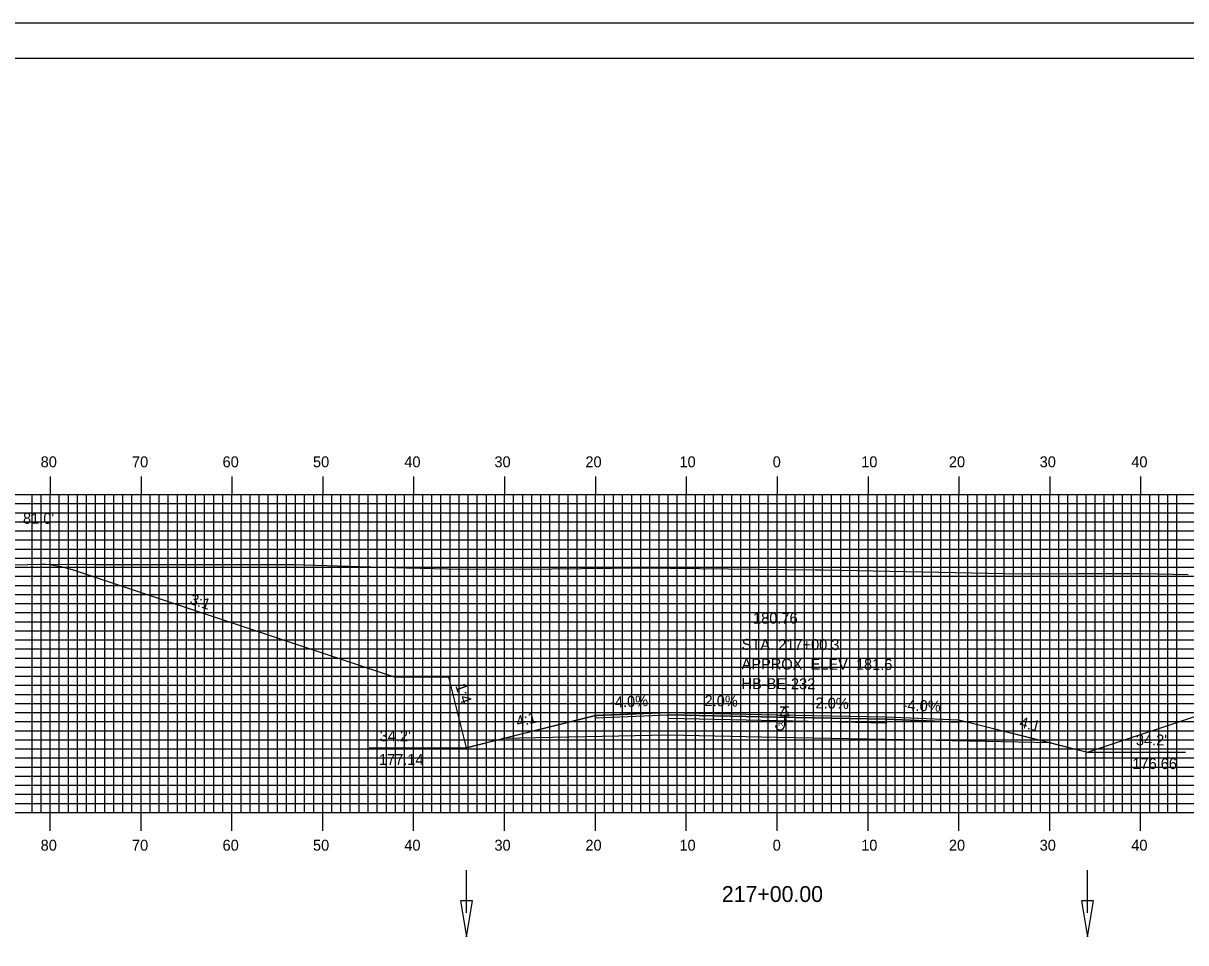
# Model space of a CAD drawing. Extents: x 1796420 to 1796763, y 442591 to 442811.
# Drawn here: x 1796502.9 to 1796630.9, y 442709.3 to 442810.5 of the extents above; entities that cross this region are included whole.
import ezdxf

# ---------------------------------------------------------------- set-up
doc = ezdxf.new("R2010")
doc.units = 0
for name, color, linetype in [('ANNOTATION', 7, 'Continuous'), ('BORDER', 7, 'Continuous'), ('BORING - REFUSAL', 7, 'Continuous'), ('D_Drainage_Ditch_Line', 7, 'Continuous'), ('D_Roadway_Centerline', 7, 'Continuous'), ('D_Roadway_Centerline_Text', 7, 'Continuous'), ('D_Roadway_Edge_Shoulder', 7, 'Continuous'), ('D_Roadway_Edge_TW', 7, 'Continuous'), ('D_Roadway_Pavement', 7, 'Continuous'), ('D_Roadway_SlopeLines', 7, 'Continuous'), ('D_Roadway_SubGrade', 7, 'Continuous'), ('D_Text_Standard', 7, 'Continuous'), ('H_V ANNOTATION', 7, 'Continuous'), ('MAJOR', 7, 'Continuous'), ('MINOR', 7, 'Continuous'), ('PDRAIN', 7, 'Continuous'), ('PLOT BOUNDARY', 7, 'Continuous'), ('S_Roadway_Centerline', 7, 'Continuous')]:
    doc.layers.add(name, color=color, linetype=linetype)

msp = doc.modelspace()

# ---------------------------------------------------------------- linework, layer by layer
at = {"layer": 'BORDER'}
msp.add_lwpolyline([(1796436.31, 442596.67), (1796756.31, 442596.67), (1796756.31, 442806.67), (1796436.31, 442806.67)], close=True, dxfattribs=at)
at = {"layer": 'BORING - REFUSAL'}
for p, q in [((1796587.19, 442735.27), (1796586.23, 442735.27)), ((1796586.71, 442734.31), (1796586.71, 442733.25))]:
    msp.add_line(p, q, dxfattribs=at)
msp.add_lwpolyline([(1796586.71, 442735.27), (1796587.19, 442734.31), (1796586.23, 442734.31)], close=True, dxfattribs=at)
msp.add_arc((1796586.22, 442733.25), 0.485, 180, 0, dxfattribs=at)
at = {"layer": 'D_Drainage_Ditch_Line'}
for p, q in [((1796551.73, 442712.63), (1796551.73, 442717.33)), ((1796620.08, 442712.63), (1796620.08, 442717.33))]:
    msp.add_line(p, q, dxfattribs=at)
for points in [[(1796552.39, 442713.94), (1796551.08, 442713.94), (1796551.73, 442710)], [(1796620.74, 442713.94), (1796619.42, 442713.94), (1796620.08, 442710)]]:
    msp.add_lwpolyline(points, close=True, dxfattribs=at)
at = {"layer": 'D_Roadway_Centerline'}
msp.add_lwpolyline([(1796551.73, 442730.8), (1796555.73, 442731.8), (1796565.91, 442734.35), (1796573.91, 442734.67), (1796585.91, 442734.43), (1796597.91, 442734.19), (1796605.91, 442733.87), (1796616.08, 442731.32), (1796620.08, 442730.32)], dxfattribs=at)
at = {"layer": 'D_Roadway_Edge_Shoulder'}
for points in [[(1796573.91, 442734.67), (1796565.91, 442734.35), (1796565.91, 442734.1), (1796573.91, 442734.42)], [(1796597.91, 442734.19), (1796605.91, 442733.87), (1796605.91, 442733.62), (1796597.91, 442733.94)]]:
    msp.add_lwpolyline(points, close=True, dxfattribs=at)
at = {"layer": 'D_Roadway_Edge_TW'}
msp.add_lwpolyline([(1796573.91, 442734.42), (1796573.91, 442734.67), (1796585.91, 442734.43), (1796597.91, 442734.19), (1796597.91, 442733.94), (1796585.91, 442734.18)], close=True, dxfattribs=at)
at = {"layer": 'D_Roadway_Pavement'}
msp.add_lwpolyline([(1796573.91, 442734), (1796573.91, 442734.42), (1796585.91, 442734.18), (1796597.91, 442733.94), (1796597.91, 442733.52), (1796585.91, 442733.76)], close=True, dxfattribs=at)
at = {"layer": 'D_Roadway_SlopeLines'}
for p, q in [((1796620.08, 442730.32), (1796673.79, 442748.23)), ((1796551.73, 442730.8), (1796549.79, 442738.57))]:
    msp.add_line(p, q, dxfattribs=at)
for points in [[(1796549.79, 442738.57), (1796543.79, 442738.57), (1796508.38, 442750.37)], [(1796565.91, 442734.35), (1796551.73, 442730.8)], [(1796605.91, 442733.87), (1796620.08, 442730.32)]]:
    msp.add_lwpolyline(points, dxfattribs=at)
msp.add_arc((1796504.61, 442739.05), 11.93, 71.5651, 88.398, dxfattribs=at)
at = {"layer": 'D_Roadway_SubGrade'}
msp.add_lwpolyline([(1796573.91, 442732.17), (1796555.73, 442731.8), (1796565.91, 442734.35), (1796565.91, 442734.1), (1796573.91, 442734.42), (1796585.91, 442734.18), (1796597.91, 442733.94), (1796605.91, 442733.62), (1796605.91, 442733.87), (1796616.08, 442731.32), (1796597.91, 442731.69), (1796585.91, 442731.93)], close=True, dxfattribs=at)
at = {"layer": 'MAJOR'}
for p, q in [((1796505.91, 442760.67), (1796505.91, 442758.67)), ((1796515.91, 442760.67), (1796515.91, 442758.67)), ((1796525.91, 442760.67), (1796525.91, 442758.67)), ((1796535.91, 442760.67), (1796535.91, 442758.67)), ((1796545.91, 442760.67), (1796545.91, 442758.67)), ((1796555.91, 442760.67), (1796555.91, 442758.67)), ((1796565.91, 442760.67), (1796565.91, 442758.67)), ((1796575.91, 442760.67), (1796575.91, 442758.67)), ((1796585.91, 442760.67), (1796585.91, 442758.67)), ((1796595.91, 442760.67), (1796595.91, 442758.67)), ((1796605.91, 442760.67), (1796605.91, 442758.67)), ((1796615.91, 442760.67), (1796615.91, 442758.67)), ((1796625.91, 442760.67), (1796625.91, 442758.67)), ((1796445.91, 442758.67), (1796725.91, 442758.67)), ((1796445.91, 442758.67), (1796725.91, 442758.67)), ((1796505.91, 442723.67), (1796505.91, 442758.67)), ((1796515.91, 442723.67), (1796515.91, 442758.67)), ((1796525.91, 442723.67), (1796525.91, 442758.67)), ((1796535.91, 442723.67), (1796535.91, 442758.67)), ((1796545.91, 442723.67), (1796545.91, 442758.67)), ((1796555.91, 442723.67), (1796555.91, 442758.67)), ((1796565.91, 442723.67), (1796565.91, 442758.67)), ((1796575.91, 442723.67), (1796575.91, 442758.67)), ((1796585.91, 442723.67), (1796585.91, 442758.67)), ((1796595.91, 442723.67), (1796595.91, 442758.67)), ((1796605.91, 442723.67), (1796605.91, 442758.67)), ((1796615.91, 442723.67), (1796615.91, 442758.67)), ((1796625.91, 442723.67), (1796625.91, 442758.67)), ((1796445.91, 442753.67), (1796725.91, 442753.67)), ((1796445.91, 442748.67), (1796725.91, 442748.67)), ((1796445.91, 442743.67), (1796725.91, 442743.67)), ((1796445.91, 442738.67), (1796725.91, 442738.67)), ((1796445.91, 442733.67), (1796725.91, 442733.67)), ((1796445.91, 442728.67), (1796725.91, 442728.67)), ((1796445.91, 442723.67), (1796725.91, 442723.67)), ((1796445.91, 442723.67), (1796725.91, 442723.67)), ((1796505.91, 442721.66), (1796505.91, 442723.67)), ((1796515.91, 442721.66), (1796515.91, 442723.67)), ((1796525.91, 442721.66), (1796525.91, 442723.67)), ((1796535.91, 442721.66), (1796535.91, 442723.67)), ((1796545.91, 442721.66), (1796545.91, 442723.67)), ((1796555.91, 442721.66), (1796555.91, 442723.67)), ((1796565.91, 442721.66), (1796565.91, 442723.67)), ((1796575.91, 442721.66), (1796575.91, 442723.67)), ((1796585.91, 442721.66), (1796585.91, 442723.67)), ((1796595.91, 442721.66), (1796595.91, 442723.67)), ((1796605.91, 442721.66), (1796605.91, 442723.67)), ((1796615.91, 442721.66), (1796615.91, 442723.67)), ((1796625.91, 442721.66), (1796625.91, 442723.67))]:
    msp.add_line(p, q, dxfattribs=at)
at = {"layer": 'MINOR'}
for p, q in [((1796503.91, 442723.67), (1796503.91, 442758.67)), ((1796504.91, 442723.67), (1796504.91, 442758.67)), ((1796506.91, 442723.67), (1796506.91, 442758.67)), ((1796507.91, 442723.67), (1796507.91, 442758.67)), ((1796508.91, 442723.67), (1796508.91, 442758.67)), ((1796509.91, 442723.67), (1796509.91, 442758.67)), ((1796510.91, 442723.67), (1796510.91, 442758.67)), ((1796511.91, 442723.67), (1796511.91, 442758.67)), ((1796512.91, 442723.67), (1796512.91, 442758.67)), ((1796513.91, 442723.67), (1796513.91, 442758.67)), ((1796514.91, 442723.67), (1796514.91, 442758.67)), ((1796516.91, 442723.67), (1796516.91, 442758.67)), ((1796517.91, 442723.67), (1796517.91, 442758.67)), ((1796518.91, 442723.67), (1796518.91, 442758.67)), ((1796519.91, 442723.67), (1796519.91, 442758.67)), ((1796520.91, 442723.67), (1796520.91, 442758.67)), ((1796521.91, 442723.67), (1796521.91, 442758.67)), ((1796522.91, 442723.67), (1796522.91, 442758.67)), ((1796523.91, 442723.67), (1796523.91, 442758.67)), ((1796524.91, 442723.67), (1796524.91, 442758.67)), ((1796526.91, 442723.67), (1796526.91, 442758.67)), ((1796527.91, 442723.67), (1796527.91, 442758.67)), ((1796528.91, 442723.67), (1796528.91, 442758.67)), ((1796529.91, 442723.67), (1796529.91, 442758.67)), ((1796530.91, 442723.67), (1796530.91, 442758.67)), ((1796531.91, 442723.67), (1796531.91, 442758.67)), ((1796532.91, 442723.67), (1796532.91, 442758.67)), ((1796533.91, 442723.67), (1796533.91, 442758.67)), ((1796534.91, 442723.67), (1796534.91, 442758.67)), ((1796536.91, 442723.67), (1796536.91, 442758.67)), ((1796537.91, 442723.67), (1796537.91, 442758.67)), ((1796538.91, 442723.67), (1796538.91, 442758.67)), ((1796539.91, 442723.67), (1796539.91, 442758.67)), ((1796540.91, 442723.67), (1796540.91, 442758.67)), ((1796541.91, 442723.67), (1796541.91, 442758.67)), ((1796542.91, 442723.67), (1796542.91, 442758.67)), ((1796543.91, 442723.67), (1796543.91, 442758.67)), ((1796544.91, 442723.67), (1796544.91, 442758.67)), ((1796546.91, 442723.67), (1796546.91, 442758.67)), ((1796547.91, 442723.67), (1796547.91, 442758.67)), ((1796548.91, 442723.67), (1796548.91, 442758.67)), ((1796549.91, 442723.67), (1796549.91, 442758.67)), ((1796550.91, 442723.67), (1796550.91, 442758.67)), ((1796551.91, 442723.67), (1796551.91, 442758.67)), ((1796552.91, 442723.67), (1796552.91, 442758.67)), ((1796553.91, 442723.67), (1796553.91, 442758.67)), ((1796554.91, 442723.67), (1796554.91, 442758.67)), ((1796556.91, 442723.67), (1796556.91, 442758.67)), ((1796557.91, 442723.67), (1796557.91, 442758.67)), ((1796558.91, 442723.67), (1796558.91, 442758.67)), ((1796559.91, 442723.67), (1796559.91, 442758.67)), ((1796560.91, 442723.67), (1796560.91, 442758.67)), ((1796561.91, 442723.67), (1796561.91, 442758.67)), ((1796562.91, 442723.67), (1796562.91, 442758.67)), ((1796563.91, 442723.67), (1796563.91, 442758.67)), ((1796564.91, 442723.67), (1796564.91, 442758.67)), ((1796566.91, 442723.67), (1796566.91, 442758.67)), ((1796567.91, 442723.67), (1796567.91, 442758.67)), ((1796568.91, 442723.67), (1796568.91, 442758.67)), ((1796569.91, 442723.67), (1796569.91, 442758.67)), ((1796570.91, 442723.67), (1796570.91, 442758.67)), ((1796571.91, 442723.67), (1796571.91, 442758.67)), ((1796572.91, 442723.67), (1796572.91, 442758.67)), ((1796573.91, 442723.67), (1796573.91, 442758.67)), ((1796574.91, 442723.67), (1796574.91, 442758.67)), ((1796576.91, 442723.67), (1796576.91, 442758.67)), ((1796577.91, 442723.67), (1796577.91, 442758.67)), ((1796578.91, 442723.67), (1796578.91, 442758.67)), ((1796579.91, 442723.67), (1796579.91, 442758.67)), ((1796580.91, 442723.67), (1796580.91, 442758.67)), ((1796581.91, 442723.67), (1796581.91, 442758.67)), ((1796582.91, 442723.67), (1796582.91, 442758.67)), ((1796583.91, 442723.67), (1796583.91, 442758.67)), ((1796584.91, 442723.67), (1796584.91, 442758.67)), ((1796586.91, 442723.67), (1796586.91, 442758.67)), ((1796587.91, 442723.67), (1796587.91, 442758.67)), ((1796588.91, 442723.67), (1796588.91, 442758.67)), ((1796589.91, 442723.67), (1796589.91, 442758.67)), ((1796590.91, 442723.67), (1796590.91, 442758.67)), ((1796591.91, 442723.67), (1796591.91, 442758.67)), ((1796592.91, 442723.67), (1796592.91, 442758.67)), ((1796593.91, 442723.67), (1796593.91, 442758.67)), ((1796594.91, 442723.67), (1796594.91, 442758.67)), ((1796596.91, 442723.67), (1796596.91, 442758.67)), ((1796597.91, 442723.67), (1796597.91, 442758.67)), ((1796598.91, 442723.67), (1796598.91, 442758.67)), ((1796599.91, 442723.67), (1796599.91, 442758.67)), ((1796600.91, 442723.67), (1796600.91, 442758.67)), ((1796601.91, 442723.67), (1796601.91, 442758.67)), ((1796602.91, 442723.67), (1796602.91, 442758.67)), ((1796603.91, 442723.67), (1796603.91, 442758.67)), ((1796604.91, 442723.67), (1796604.91, 442758.67)), ((1796606.91, 442723.67), (1796606.91, 442758.67)), ((1796607.91, 442723.67), (1796607.91, 442758.67)), ((1796608.91, 442723.67), (1796608.91, 442758.67)), ((1796609.91, 442723.67), (1796609.91, 442758.67)), ((1796610.91, 442723.67), (1796610.91, 442758.67)), ((1796611.91, 442723.67), (1796611.91, 442758.67)), ((1796612.91, 442723.67), (1796612.91, 442758.67)), ((1796613.91, 442723.67), (1796613.91, 442758.67)), ((1796614.91, 442723.67), (1796614.91, 442758.67)), ((1796616.91, 442723.67), (1796616.91, 442758.67)), ((1796617.91, 442723.67), (1796617.91, 442758.67)), ((1796618.91, 442723.67), (1796618.91, 442758.67)), ((1796619.91, 442723.67), (1796619.91, 442758.67)), ((1796620.91, 442723.67), (1796620.91, 442758.67)), ((1796621.91, 442723.67), (1796621.91, 442758.67)), ((1796622.91, 442723.67), (1796622.91, 442758.67)), ((1796623.91, 442723.67), (1796623.91, 442758.67)), ((1796624.91, 442723.67), (1796624.91, 442758.67)), ((1796626.91, 442723.67), (1796626.91, 442758.67)), ((1796627.91, 442723.67), (1796627.91, 442758.67)), ((1796628.91, 442723.67), (1796628.91, 442758.67)), ((1796629.91, 442723.67), (1796629.91, 442758.67)), ((1796445.91, 442757.67), (1796725.91, 442757.67)), ((1796445.91, 442756.67), (1796725.91, 442756.67)), ((1796445.91, 442755.67), (1796725.91, 442755.67)), ((1796445.91, 442754.67), (1796725.91, 442754.67)), ((1796445.91, 442752.67), (1796725.91, 442752.67)), ((1796445.91, 442751.67), (1796725.91, 442751.67)), ((1796445.91, 442750.67), (1796725.91, 442750.67)), ((1796445.91, 442749.67), (1796725.91, 442749.67)), ((1796445.91, 442747.67), (1796725.91, 442747.67)), ((1796445.91, 442746.67), (1796725.91, 442746.67)), ((1796445.91, 442745.67), (1796725.91, 442745.67)), ((1796445.91, 442744.67), (1796725.91, 442744.67)), ((1796445.91, 442742.67), (1796725.91, 442742.67)), ((1796445.91, 442741.67), (1796725.91, 442741.67)), ((1796445.91, 442740.67), (1796725.91, 442740.67)), ((1796445.91, 442739.67), (1796725.91, 442739.67)), ((1796445.91, 442737.67), (1796725.91, 442737.67)), ((1796445.91, 442736.67), (1796725.91, 442736.67)), ((1796445.91, 442735.67), (1796725.91, 442735.67)), ((1796445.91, 442734.67), (1796725.91, 442734.67)), ((1796445.91, 442732.67), (1796725.91, 442732.67)), ((1796445.91, 442731.67), (1796725.91, 442731.67)), ((1796445.91, 442730.67), (1796725.91, 442730.67)), ((1796445.91, 442729.67), (1796725.91, 442729.67)), ((1796445.91, 442727.67), (1796725.91, 442727.67)), ((1796445.91, 442726.67), (1796725.91, 442726.67)), ((1796445.91, 442725.67), (1796725.91, 442725.67)), ((1796445.91, 442724.67), (1796725.91, 442724.67))]:
    msp.add_line(p, q, dxfattribs=at)
at = {"layer": 'PDRAIN'}
for p, q in [((1796541.01, 442730.8), (1796551.73, 442730.8)), ((1796620.08, 442730.32), (1796630.85, 442730.32))]:
    msp.add_line(p, q, dxfattribs=at)
at = {"layer": 'PLOT BOUNDARY'}
msp.add_lwpolyline([(1796420.12, 442590.55), (1796760.12, 442590.55), (1796760.12, 442810.55), (1796420.12, 442810.55)], close=True, dxfattribs=at)
at = {"layer": 'S_Roadway_Centerline'}
msp.add_lwpolyline([(1796491.21, 442750.88), (1796503.46, 442750.97), (1796507.95, 442750.99), (1796510.98, 442750.98), (1796519.86, 442750.95), (1796531.21, 442750.96), (1796531.82, 442750.97), (1796532.71, 442750.95), (1796543.62, 442750.62), (1796551.14, 442750.46), (1796561.13, 442750.48), (1796571, 442750.6), (1796590.14, 442750.39), (1796590.66, 442750.39), (1796591.01, 442750.38), (1796592.93, 442750.35), (1796610.9, 442749.96), (1796614.17, 442749.95), (1796618.88, 442749.98), (1796626.07, 442749.97), (1796631.13, 442749.85)], dxfattribs=at)

# ---------------------------------------------------------------- texts
at = {"layer": 'ANNOTATION'}
for s, rotation, p in [('3:1', 341.5651, (1796521.19, 442746.66)), ('3:1', 341.5651, (1796521.19, 442746.66)), ('1:4', 289.484, (1796550.47, 442737.63)), ('-4.0%', 2.2906, (1796567.54, 442735.21)), ('2.0%', 358.8542, (1796577.91, 442735.39)), ('-2.0%', 358.8542, (1796589.59, 442735.15)), ('-4.0%', 357.7094, (1796599.7, 442734.92)), ('4:1', 14.0362, (1796557.35, 442733.07)), ('4:1', 345.9638, (1796612.5, 442733.08))]:
    msp.add_text(s, height=1.2, rotation=rotation, dxfattribs=at).set_placement(p)
for s, p in [("34.2'", (1796542.17, 442731.5)), ("34.2'", (1796625.39, 442731.05)), ('177.14', (1796542.09, 442728.9)), ('176.66', (1796625, 442728.45))]:
    msp.add_text(s, height=1.2, dxfattribs=at).set_placement(p)
at = {"layer": 'BORING - REFUSAL'}
for s, p in [('STA. 217+00.3', (1796582.01, 442741.58)), ('APPROX. ELEV. 181.6', (1796582, 442739.42)), ('HB-BE-232', (1796581.99, 442737.26))]:
    msp.add_text(s, height=1.2, rotation=359.8142, dxfattribs=at).set_placement(p)
msp.add_text('R', height=0.64, dxfattribs=at).set_placement((1796586, 442733.19))
at = {"layer": 'D_Roadway_Centerline'}
for s, p in [('C', (1796585.9, 442734.43)), ('L', (1796585.91, 442734.42))]:
    msp.add_text(s, height=0.0146, dxfattribs=at).set_placement(p)
at = {"layer": 'D_Roadway_Centerline_Text'}
msp.add_text('180.76', height=1.2, dxfattribs=at).set_placement((1796583.26, 442744.46))
at = {"layer": 'D_Text_Standard'}
msp.add_text("81.0'", height=1.2, dxfattribs=at).set_placement((1796502.92, 442755.45))
at = {"layer": 'H_V ANNOTATION'}
for s, height, p in [('80', 1.2, (1796504.86, 442761.67)), ('70', 1.2, (1796514.91, 442761.67)), ('60', 1.2, (1796524.88, 442761.67)), ('50', 1.2, (1796534.83, 442761.67)), ('40', 1.2, (1796544.88, 442761.67)), ('30', 1.2, (1796554.8, 442761.67)), ('20', 1.2, (1796564.81, 442761.67)), ('10', 1.2, (1796575.16, 442761.67)), ('0', 1.2, (1796585.42, 442761.67)), ('10', 1.2, (1796595.16, 442761.67)), ('20', 1.2, (1796604.81, 442761.67)), ('30', 1.2, (1796614.8, 442761.67)), ('40', 1.2, (1796624.88, 442761.67)), ('80', 1.2, (1796504.86, 442719.47)), ('70', 1.2, (1796514.91, 442719.47)), ('60', 1.2, (1796524.88, 442719.47)), ('50', 1.2, (1796534.83, 442719.47)), ('40', 1.2, (1796544.88, 442719.47)), ('30', 1.2, (1796554.8, 442719.47)), ('20', 1.2, (1796564.81, 442719.47)), ('10', 1.2, (1796575.16, 442719.47)), ('0', 1.2, (1796585.42, 442719.47)), ('10', 1.2, (1796595.16, 442719.47)), ('20', 1.2, (1796604.81, 442719.47)), ('30', 1.2, (1796614.8, 442719.47)), ('40', 1.2, (1796624.88, 442719.47)), ('217+00.00', 1.75, (1796579.83, 442713.82))]:
    msp.add_text(s, height=height, dxfattribs=at).set_placement(p)

doc.saveas('drawing.dxf')
